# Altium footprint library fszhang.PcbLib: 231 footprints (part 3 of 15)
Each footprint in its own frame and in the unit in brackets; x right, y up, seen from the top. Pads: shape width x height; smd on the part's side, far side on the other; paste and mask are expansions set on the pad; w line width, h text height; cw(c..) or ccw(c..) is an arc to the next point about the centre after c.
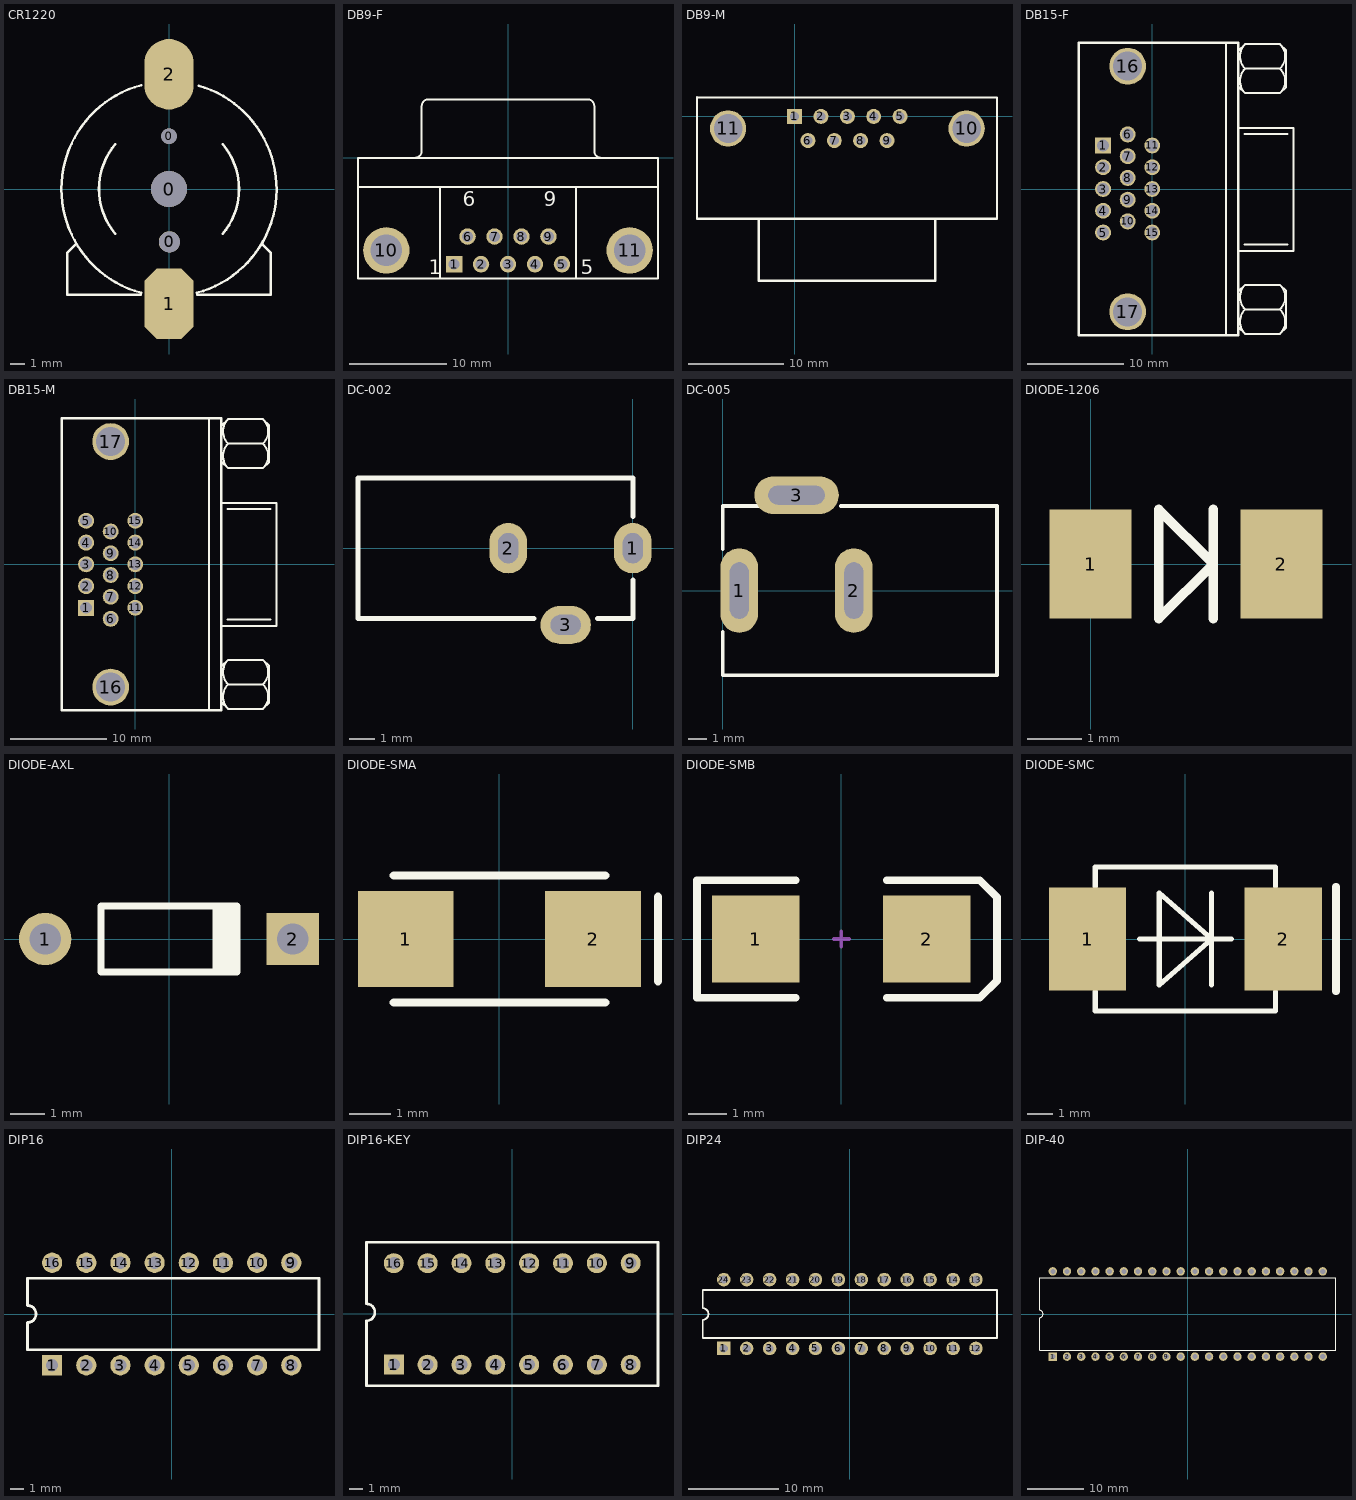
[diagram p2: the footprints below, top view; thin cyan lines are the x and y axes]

## CR1220 [mm] "钮扣电池"
height 3
pads (5):
  round 2.54 hole 2.54: 0(0,0)
  round 1.1 hole 1.1: 0(0,3.75)
  round 1.5 hole 1.5: 0(0.025,-3.75)
  oct 3.5x5 smd: 1(0,-8.128)
  oval 3.5x5 smd: 2(0,8.128)
Top Overlay:
  lines w0.178: -6.6,-3.9 -7.2,-4.5 -7.2,-7.5 -2,-7.5 ; -3.815,-3.169 cw(c0,0) -3.812,3.172 ; -1.963,-7.363 cw(c0,0) -7.62,0 cw(c0,0) -1.963,7.363 ; 1.963,-7.363 ccw(c0,0) 2.093,7.327 ; 2,-7.5 7.2,-7.5 7.2,-4.5 6.625,-3.925 ; 3.81,-3.175 ccw(c0,0) 3.812,3.172

## DB9-F [mm] "DB9母座"
height 12.75
pads (11):
  rect 1.69x1.69 hole 1.09: 1(-5.54,-10.92)
  round 1.69 hole 1.09: 2(-2.77,-10.92) 3(0,-10.92) 4(2.77,-10.92) 5(5.54,-10.92) 6(-4.155,-8.08) 7(-1.385,-8.08) 8(1.385,-8.08) 9(4.155,-8.08)
  round 4.76 hole 3.26: 10(-12.495,-9.5) 11(12.495,-9.5)
Top Overlay:
  lines w0.2: -15.4,-3 15.4,-3 ; -9.56,0.005 ccw(c-9.56,0.7) -8.865,0.7 -8.865,5.3 ; -8.86,5.305 cw(c-8.165,5.305) -8.165,6 8.165,6 cw(c8.165,5.305) 8.86,5.305 ; -7,-12.4 -7,-3 ; 7,-12.4 7,-3 ; 8.865,5.3 8.865,0.7 ccw(c9.56,0.7) 9.56,0.005 ; -15.4,-12.4 -15.4,0 15.4,0 15.4,-12.4 -15.4,-12.4
  text "1" at -8.128,-11.938 h1.5
  text "5" at 7.493,-11.938 h1.5
  text "9" at 3.655,-4.975 h1.5
  text "6" at -4.655,-4.975 h1.5

## DB9-M [mil] "DB9公座"
height 393.7
pads (11):
  rect 62x62 hole 38: 1(0,0)
  round 62 hole 38: 2(109,0) 3(218,0) 4(327,0) 5(436,0) 6(55,-100) 7(164,-100) 8(273,-100) 9(382,-100)
  round 150 hole 118.11: 10(711,-50) 11(-275,-50)
Top Overlay:
  lines w8: -403.54,78.74 836.61,78.74 836.61,-423.23
  lines w10: -403.54,78.74 -403.54,-423.23 836.61,-423.23 ; -147.64,-425 -147.64,-679.13 580.71,-679.13 580.71,-425
3D body: height 393.7, standoff 0, extent -405,-425 835,75
3D body: height 314.96, standoff 0, extent -145,-680 580,-425

## DB15-F [mil] "VGAĸ"
height 393.7
pads (17):
  rect 65x65 hole 48: 1(-200,177.16)
  round 65 hole 48: 2(-200,88.58) 3(-200,0) 4(-200,-88.58) 5(-200,-177.16) 6(-100,222.17) 7(-100,133.58) 8(-100,45) 9(-100,-43.58) 10(-100,-132.16) 11(0,177.16) 12(0,88.58) 13(0,0) 14(0,-88.58) 15(0,-177.16)
  round 150 hole 118.11: 16(-100,500) 17(-100,-500)
Top Overlay:
  lines w8: 300,-595 300,596.25 ; 350,-251.67 575,-251.67 575,248.33 350,248.33 ; 353.33,-565 378.33,-590 520,-590 545,-565 545,-415 520,-390 378.33,-390 353.33,-415 ; 353.33,415 378.33,390 520,390 545,415 545,565 520,590 378.33,590 353.33,565 ; 375,-226.67 550,-226.67 ; 375,223.33 550,223.33 ; 378.25,-590.09 cw(c428.33,-540) 378.25,-489.91 ; 378.25,-490.09 cw(c428.33,-440) 378.25,-389.91 ; 378.25,389.91 cw(c428.33,440) 378.25,490.09 ; 378.25,489.91 cw(c428.33,540) 378.25,590.09 ; 378.33,-490 520,-490 ; 378.33,490 520,490 ; 520.09,-590.09 ccw(c470,-540) 520.09,-489.91 ; 520.09,-490.09 ccw(c470,-440) 520.09,-389.91 ; 520.09,389.91 ccw(c470,440) 520.09,490.09 ; 520.09,489.91 ccw(c470,540) 520.09,590.09
  lines w10: -300,-595 350,-595 350,595 -300,595 -300,-595

## DB15-M [mil] "VGA公"
height 393.7
pads (17):
  rect 65x65 hole 48: 1(-200,-177.16)
  round 65 hole 48: 2(-200,-88.58) 3(-200,0) 4(-200,88.58) 5(-200,177.16) 6(-100,-222) 7(-100,-132.16) 8(-100,-43.58) 9(-100,45) 10(-100,133.58) 11(0,-177.16) 12(0,-88.58) 13(0,0) 14(0,88.58) 15(0,177.16)
  round 150 hole 118.11: 16(-100,-500) 17(-100,500)
Top Overlay:
  lines w8: 300,-596.25 300,595 ; 350,-250.42 575,-250.42 575,249.58 350,249.58 ; 353.33,-563.75 378.33,-588.75 520,-588.75 545,-563.75 545,-413.75 520,-388.75 378.33,-388.75 353.33,-413.75 ; 353.33,416.25 378.33,391.25 520,391.25 545,416.25 545,566.25 520,591.25 378.33,591.25 353.33,566.25 ; 375,-225.42 550,-225.42 ; 375,224.58 550,224.58 ; 378.25,-588.84 cw(c428.33,-538.75) 378.25,-488.66 ; 378.25,-488.84 cw(c428.33,-438.75) 378.25,-388.66 ; 378.25,391.16 cw(c428.33,441.25) 378.25,491.34 ; 378.25,491.16 cw(c428.33,541.25) 378.25,591.34 ; 378.33,-488.75 520,-488.75 ; 378.33,491.25 520,491.25 ; 520.09,-588.84 ccw(c470,-538.75) 520.09,-488.66 ; 520.09,-488.84 ccw(c470,-438.75) 520.09,-388.66 ; 520.09,391.16 ccw(c470,441.25) 520.09,491.34 ; 520.09,491.16 ccw(c470,541.25) 520.09,591.34
  lines w10: -300,-595 350,-595 350,595 -300,595 -300,-595

## DC-002 [mm] "DC母座3.5mm"
height 7.2
pads (3):
  oval 1.5x2 hole 0.8 slot 1.2 at 90 deg: 1(0,0) 2(-4.953,0)
  oval 2x1.5 hole 0.8 slot 1.2 at 0 deg: 3(-2.667,-3.048)
Top Overlay:
  lines w0.2: -3.937,-2.794 -10.922,-2.794 -10.922,2.794 0,2.794 0,1.27 ; -1.397,-2.794 0,-2.794 0,-1.27
3D body: height 7.2, standoff 0, extent -10.922,-2.794 0,2.794

## DC-005 [mm] "DC母座5.5mm"
height 12.75
pads (3):
  oval 2x4.5 hole 1 slot 3 at 90 deg: 1(0.889,0) 2(6.985,0)
  oval 4.5x2 hole 1 slot 3 at 0 deg: 3(3.937,5.08)
Top Overlay:
  lines w0.2: 0.005,-2.2 0.005,-4.5 14.605,-4.5 14.605,4.5 6.305,4.5 ; 0.005,2.2 0.005,4.5 1.905,4.5
3D body: height 11, standoff 0, extent 0,-4.445 14.605,4.445

## DIODE-1206 [mm] "玻璃封装二极管"
height 3
pads (2):
  rect 1.5x2 smd: 1(0,0) 2(3.5,0)
Top Overlay:
  lines w0.178: 2.25,-1 2.25,1 ; 1.25,-1 1.25,1 2.25,0 1.25,-1

## DIODE-AXL [mm] "直插二极管"
height 1.9
pads (2):
  round 1.5 hole 0.9: 1(-3.55,0)
  rect 1.5x1.5 hole 0.9: 2(3.55,0)
Top Overlay:
  rectangle: 1.25,-0.95 2.05,0.95
  lines w0.2: 1.95,-0.95 -1.95,-0.95 -1.95,0.95 1.95,0.95

## DIODE-SMA [mm] "贴片二极管"
height 2.54
pads (2):
  rect 2.3x2.3 smd: 1(-2.25,0) 2(2.25,0)
Top Overlay:
  lines w0.2: -2.54,-1.524 2.54,-1.524 ; -2.54,1.524 2.54,1.524 ; 3.81,-1.016 3.81,1.016
3D body: height 3, standoff 0, extent -2.921,-1.397 2.921,1.397

## DIODE-SMB [mm] "DO-214-AA/SMB; 2 C-Bend Leads; Body 5.3 x 3.6 mm, inc. leads (LxW)"
height 2.54
pads (2):
  rect 2.3x2.3 smd: 1(-2.25,0) 2(2.25,0)
Top Overlay:
  lines w0.2: -1.2,-1.55 -3.8,-1.55 -3.8,1.55 -1.2,1.55 ; 1.2,-1.55 3.65,-1.55 4.1,-1.1 4.1,1.1 3.65,1.55 1.2,1.55
Mechanical 1:
  lines w0.1: -0.2,0 0.2,0 ; 0,-0.2 0,0.2

## DIODE-SMC [mm] "贴片二极管"
height 1.5
pads (2):
  rect 3x4 smd: 1(-3.8,0) 2(3.8,0)
Top Overlay:
  lines w0.2: -3.5,-2.032 -3.5,-2.794 3.5,-2.794 3.5,-2.032 ; -3.5,2.032 -3.5,2.794 3.5,2.794 3.5,2.032 ; -1.778,0 1.778,0 ; 1.016,-1.778 1.016,1.778 ; -1.016,-1.778 1.016,0 -1.016,1.778 -1.016,-1.778
  lines w0.3: 5.842,-2.032 5.842,2.032
3D body: height 1.05, standoff 1, extent 2.921,-2.794 3.429,2.794
3D body: height 1, standoff 0, extent -3.429,-2.794 3.556,2.794
3D body: height 0.8, standoff 0, extent 3.556,-1.905 3.937,1.905
3D body: height 0.8, standoff 0, extent -3.81,-1.905 -3.429,1.905

## DIP16 [mm]
height 5.8
pads (16):
  rect 1.5x1.5 hole 0.9: 1(-8.89,-3.81)
  round 1.5 hole 0.9: 2(-6.35,-3.81) 3(-3.81,-3.81) 4(-1.27,-3.81) 5(1.27,-3.81) 6(3.81,-3.81) 7(6.35,-3.81) 8(8.89,-3.81) 9(8.89,3.81) 10(6.35,3.81) 11(3.81,3.81) 12(1.27,3.81) 13(-1.27,3.81) 14(-3.81,3.81) 15(-6.35,3.81) 16(-8.89,3.81)
Top Overlay:
  lines w0.2: -10.716,-2.65 10.95,-2.65 10.95,2.65 -10.716,2.65 -10.716,0.635 cw(c-10.716,0) -10.716,-0.635 -10.716,-2.65

## DIP16-KEY [mm] "DIP拨码开关"
height 2.65
pads (16):
  rect 1.5x1.5 hole 0.9: 1(-8.89,-3.81)
  round 1.5 hole 0.9: 2(-6.35,-3.81) 3(-3.81,-3.81) 4(-1.27,-3.81) 5(1.27,-3.81) 6(3.81,-3.81) 7(6.35,-3.81) 8(8.89,-3.81) 9(8.89,3.81) 10(6.35,3.81) 11(3.81,3.81) 12(1.27,3.81) 13(-1.27,3.81) 14(-3.81,3.81) 15(-6.35,3.81) 16(-8.89,3.81)
Top Overlay:
  lines w0.2: -10.94,0.76 cw(c-10.94,0.125) -10.94,-0.51 -10.94,-5.4 10.94,-5.4 10.94,5.39 -10.94,5.39 -10.94,0.79

## DIP24 [mm] "DIP; 24,74ls154"
height 5.08
pads (24):
  rect 1.5x1.5 hole 0.9: 1(-13.97,-3.81)
  round 1.5 hole 0.9: 2(-11.43,-3.81) 3(-8.89,-3.81) 4(-6.35,-3.81) 5(-3.81,-3.81) 6(-1.27,-3.81) 7(1.27,-3.81) 8(3.81,-3.81) 9(6.35,-3.81) 10(8.89,-3.81) 11(11.43,-3.81) 12(13.97,-3.81) 13(13.97,3.81) 14(11.43,3.81) 15(8.89,3.81) 16(6.35,3.81) 17(3.81,3.81) 18(1.27,3.81) 19(-1.27,3.81) 20(-3.81,3.81) 21(-6.35,3.81) 22(-8.89,3.81) 23(-11.43,3.81) 24(-13.97,3.81)
Top Overlay:
  lines w0.2: -16.3,-2.65 -16.3,-0.635 ccw(c-16.3,0) -16.3,0.635 -16.3,2.65 16.3,2.65 16.3,-2.65 -16.3,-2.65

## DIP-40 [mm] "51单片机"
height 4.7
pads (40):
  rect 1.5x1.5 hole 0.9: 1(-24.13,-7.62)
  round 1.5 hole 0.9: 2(-21.59,-7.62) 3(-19.05,-7.62) 4(-16.51,-7.62) 5(-13.97,-7.62) 6(-11.43,-7.62) 7(-8.89,-7.62) 8(-6.35,-7.62) 9(-3.81,-7.62) 10(-1.27,-7.62) 11(1.27,-7.62) 12(3.81,-7.62) 13(6.35,-7.62) 14(8.89,-7.62) 15(11.43,-7.62) 16(13.97,-7.62) 17(16.51,-7.62) 18(19.05,-7.62) 19(21.59,-7.62) 20(24.13,-7.62) 21(24.13,7.62) 22(21.59,7.62) 23(19.05,7.62) 24(16.51,7.62) 25(13.97,7.62) 26(11.43,7.62) 27(8.89,7.62) 28(6.35,7.62) 29(3.81,7.62) 30(1.27,7.62) 31(-1.27,7.62) 32(-3.81,7.62) 33(-6.35,7.62) 34(-8.89,7.62) 35(-11.43,7.62) 36(-13.97,7.62) 37(-16.51,7.62) 38(-19.05,7.62) 39(-21.59,7.62) 40(-24.13,7.62)
Top Overlay:
  lines w0.2: -26.5,-6.45 26.5,-6.45 26.5,6.45 -26.5,6.45 -26.5,0.635 cw(c-26.5,0) -26.5,-0.635 -26.5,-6.45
